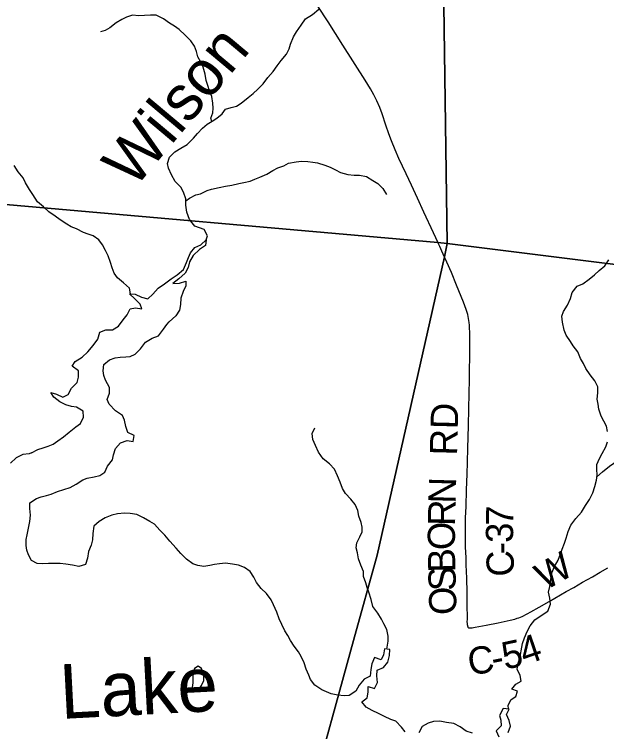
# Model space of a CAD drawing. Extents: x 0 to 34, y 0 to 22.
# Drawn here: x 3.583 to 4.817, y 18.585 to 20.079 of the extents above; entities that cross this region are included whole.
import ezdxf

# ---------------------------------------------------------------- set-up
doc = ezdxf.new("R2010")
doc.units = 0
for name, color, linetype in [('GM_X_County_Road', 7, 'Continuous'), ('GM_X_County_Road_Text', 7, 'Continuous'), ('GM_X_Major_Lake', 7, 'Continuous'), ('GM_X_Major_Lake_Text', 7, 'Continuous'), ('GM_X_Minor_River', 7, 'Continuous'), ('GM_X_Minor_River_Text', 7, 'Continuous'), ('GM_X_Township_Road', 7, 'Continuous')]:
    doc.layers.add(name, color=color, linetype=linetype)

msp = doc.modelspace()

# ---------------------------------------------------------------- linework, layer by layer
at = {"layer": 'GM_X_County_Road'}
msp.add_line((4.5241, 18.9388), (4.5239, 18.9467), dxfattribs=at)
for points in [[(4.466, 19.6027), (4.4656, 19.6036), (4.4562, 19.6242), (4.4362, 19.667), (4.4225, 19.6965), (4.41, 19.7233), (4.3991, 19.747), (4.3842, 19.7792), (4.3762, 19.7973), (4.3684, 19.8162), (4.3629, 19.8307), (4.3571, 19.8483), (4.3492, 19.8719), (4.3442, 19.8853), (4.338, 19.8996), (4.3319, 19.9119), (4.3249, 19.9244), (4.3138, 19.9424), (4.2676, 20.0153), (4.2365, 20.064), (4.215, 20.0967)], [(4.4791, 19.5737), (4.4736, 19.5858), (4.4694, 19.5954), (4.466, 19.6027)], [(4.5239, 18.9467), (4.523, 18.9697), (4.5227, 18.9921), (4.5231, 19.0305), (4.5239, 19.0542), (4.5251, 19.0887), (4.5263, 19.1212), (4.5272, 19.146), (4.5277, 19.1752), (4.5292, 19.2218), (4.5301, 19.2578), (4.5313, 19.3193), (4.5322, 19.3843), (4.5322, 19.3992), (4.5321, 19.405), (4.5318, 19.4172), (4.5315, 19.4256), (4.5312, 19.4316), (4.5306, 19.4374), (4.53, 19.4413), (4.5294, 19.4454), (4.5275, 19.454), (4.5244, 19.4642), (4.5186, 19.48), (4.5044, 19.5151), (4.4934, 19.5415), (4.4839, 19.5631), (4.4791, 19.5737)], [(4.5291, 18.8011), (4.5286, 18.802), (4.5283, 18.8028), (4.5279, 18.8039), (4.5275, 18.8056), (4.5273, 18.8068), (4.5271, 18.8094), (4.5266, 18.8143), (4.5267, 18.8183), (4.5268, 18.825), (4.5269, 18.8301), (4.5266, 18.8401), (4.5266, 18.8748), (4.5256, 18.9046), (4.5244, 18.9326), (4.5241, 18.9388)], [(4.5291, 18.8011), (4.5304, 18.8008), (4.531, 18.8007), (4.5318, 18.8007), (4.5331, 18.8007), (4.5345, 18.8008), (4.5359, 18.801), (4.537, 18.8011), (4.5393, 18.8015), (4.5431, 18.8022), (4.5503, 18.8037), (4.5659, 18.8068), (4.5908, 18.8117), (4.6157, 18.8168), (4.6258, 18.8194), (4.6306, 18.8209), (4.634, 18.822), (4.6377, 18.8235), (4.6408, 18.8249), (4.6513, 18.8301), (4.659, 18.8342), (4.6762, 18.8441), (4.6972, 18.8562), (4.7327, 18.8767), (4.7484, 18.8854), (4.7667, 18.8959), (4.7871, 18.9075), (4.8032, 18.9168), (4.8193, 18.9261)]]:
    msp.add_lwpolyline(points, dxfattribs=at)
at = {"layer": 'GM_X_Major_Lake'}
for points in [[(3.6188, 19.1659), (3.6319, 19.1726), (3.6429, 19.1761), (3.6532, 19.1797), (3.6636, 19.1841), (3.6732, 19.1907), (3.6851, 19.1992), (3.697, 19.2085), (3.7113, 19.2196), (3.7209, 19.227), (3.7272, 19.2397), (3.7263, 19.2523), (3.7121, 19.2609), (3.7023, 19.2626), (3.6899, 19.2659), (3.6775, 19.2722), (3.6652, 19.2819), (3.6589, 19.2915), (3.671, 19.2883), (3.6841, 19.2819), (3.6952, 19.287), (3.7023, 19.3002), (3.7135, 19.3125), (3.7168, 19.3234), (3.7163, 19.3367), (3.7032, 19.3461), (3.7095, 19.3558), (3.7241, 19.365), (3.7357, 19.3765), (3.7473, 19.3892), (3.7567, 19.4023), (3.7608, 19.417), (3.7734, 19.4217), (3.7874, 19.4218), (3.8001, 19.4299), (3.8094, 19.4426), (3.818, 19.4534), (3.8239, 19.4655), (3.8353, 19.4679), (3.8482, 19.4661), (3.8453, 19.4757), (3.8342, 19.4865), (3.823, 19.497), (3.8348, 19.4967), (3.8479, 19.4904), (3.8607, 19.4867), (3.8715, 19.4964), (3.8824, 19.5087), (3.8958, 19.5179), (3.9097, 19.5283), (3.9223, 19.5367), (3.9351, 19.5475), (3.9414, 19.5625), (3.9454, 19.5727), (3.9498, 19.5825), (3.9587, 19.5937), (3.9717, 19.5991), (3.9822, 19.6095), (3.9808, 19.5978), (3.9689, 19.5893), (3.9554, 19.5767), (3.9479, 19.5639), (3.945, 19.5522), (3.9387, 19.5398), (3.9256, 19.5283), (3.9129, 19.5187), (3.9269, 19.5196), (3.9403, 19.5235), (3.9401, 19.514), (3.9345, 19.5016), (3.9297, 19.488), (3.929, 19.4751), (3.9269, 19.463), (3.9191, 19.451), (3.9056, 19.4388)], [(3.6288, 19.0708), (3.6391, 19.0743), (3.6498, 19.0767), (3.6593, 19.0798), (3.6731, 19.0848), (3.6861, 19.0893), (3.6991, 19.0935), (3.7118, 19.1004), (3.7253, 19.1095), (3.7349, 19.1126), (3.749, 19.1157), (3.7608, 19.1187), (3.7713, 19.1257), (3.7769, 19.1376), (3.7875, 19.1514), (3.7897, 19.1616), (3.7939, 19.1744), (3.8041, 19.1866), (3.8178, 19.1911), (3.8303, 19.1893), (3.8322, 19.2021), (3.8195, 19.2082), (3.8149, 19.2208), (3.8126, 19.2338), (3.808, 19.2438), (3.7938, 19.2533), (3.7806, 19.2669), (3.7763, 19.2769), (3.7809, 19.2904), (3.7812, 19.3022), (3.7726, 19.3172), (3.7694, 19.3268), (3.7682, 19.3363), (3.769, 19.3496), (3.7814, 19.3595), (3.7932, 19.3637), (3.8035, 19.3649), (3.8149, 19.3657), (3.8244, 19.3666), (3.8344, 19.3716), (3.8457, 19.3827), (3.8563, 19.3965), (3.8702, 19.4044), (3.8832, 19.4094), (3.8938, 19.4235), (3.9009, 19.4332), (3.9056, 19.4388)], [(3.6188, 19.1659), (3.6136, 19.1638), (3.6007, 19.1623), (3.5869, 19.1554), (3.5748, 19.1444)], [(4.318, 18.6549), (4.3199, 18.667), (4.3202, 18.6787), (4.333, 18.6746), (4.3398, 18.6869), (4.3383, 18.701), (4.3386, 18.7127), (4.3517, 18.7185), (4.3607, 18.7296), (4.3645, 18.7431), (4.3649, 18.756), (4.3543, 18.7575), (4.352, 18.7446), (4.3468, 18.7345), (4.3333, 18.7391), (4.3276, 18.7263), (4.3254, 18.7139), (4.3239, 18.7003), (4.3119, 18.6938), (4.301, 18.6815), (4.2942, 18.6692), (4.2803, 18.6601), (4.27, 18.6596), (4.2568, 18.6608), (4.2433, 18.6638), (4.2331, 18.6675), (4.2234, 18.6719), (4.2089, 18.6814), (4.1998, 18.6931), (4.1963, 18.7026), (4.1909, 18.7146), (4.1868, 18.7283), (4.1807, 18.7414), (4.1749, 18.751), (4.1662, 18.7627), (4.1582, 18.7743), (4.1524, 18.7851), (4.1466, 18.7951), (4.1402, 18.8078), (4.1349, 18.8201), (4.1296, 18.8335), (4.1228, 18.8488), (4.1182, 18.8596), (4.1083, 18.8728), (4.0973, 18.8829), (4.0874, 18.8954), (4.082, 18.9069), (4.0744, 18.9181), (4.0622, 18.9268), (4.0502, 18.9313), (4.0374, 18.9339), (4.0226, 18.9355), (4.0101, 18.9343), (3.9998, 18.9331), (3.9899, 18.9307), (3.9778, 18.9291), (3.9649, 18.931), (3.9548, 18.9343), (3.9414, 18.9438), (3.93, 18.9559), (3.9201, 18.9671), (3.9069, 18.9819), (3.8967, 18.994), (3.8863, 19.0045), (3.8746, 19.017), (3.8649, 19.0229), (3.8522, 19.0305), (3.8384, 19.0369), (3.8245, 19.0392), (3.8124, 19.0399), (3.7979, 19.0388), (3.7857, 19.0357), (3.7719, 19.0304), (3.7596, 19.0228), (3.7487, 19.0129), (3.7464, 18.9977), (3.746, 18.9841), (3.7426, 18.9732), (3.7373, 18.9601), (3.735, 18.9461), (3.7313, 18.9333), (3.7175, 18.9291), (3.7043, 18.9314), (3.6904, 18.934), (3.6783, 18.9348), (3.6635, 18.9352), (3.654, 18.9351), (3.6415, 18.9343), (3.6306, 18.9353), (3.6186, 18.941), (3.6121, 18.9533), (3.609, 18.9632), (3.6074, 18.9728), (3.6077, 18.9849), (3.6099, 18.9951), (3.6126, 19.0087), (3.6153, 19.0226), (3.6164, 19.0359), (3.6153, 19.0496), (3.6149, 19.0617), (3.6288, 19.0708)], [(3.9779, 18.699), (3.978, 18.7048), (3.9726, 18.7162), (3.9662, 18.7213), (3.9582, 18.7165), (3.9549, 18.706), (3.9548, 18.6984)], [(3.9548, 18.6984), (3.9549, 18.6866), (3.9536, 18.6764), (3.956, 18.668), (3.9656, 18.6705), (3.973, 18.6806), (3.9777, 18.6915), (3.9779, 18.699)], [(4.3971, 18.584), (4.3898, 18.5937), (4.378, 18.6062), (4.3675, 18.6103), (4.3544, 18.6163), (4.3417, 18.6224), (4.3286, 18.6288), (4.3156, 18.6356), (4.3072, 18.6468), (4.318, 18.6549)], [(4.6118, 18.583), (4.6167, 18.5958), (4.614, 18.6076), (4.6083, 18.6203), (4.614, 18.6315), (4.6015, 18.6326), (4.5935, 18.6184), (4.5963, 18.6089), (4.5974, 18.5967), (4.5865, 18.5867), (4.5922, 18.5737)], [(4.5371, 18.5817), (4.524, 18.5854), (4.5114, 18.5945), (4.4987, 18.6017), (4.4836, 18.604), (4.4693, 18.6063), (4.4564, 18.6055), (4.4449, 18.6024), (4.4326, 18.5952), (4.4258, 18.5821)]]:
    msp.add_lwpolyline(points, dxfattribs=at)
at = {"layer": 'GM_X_Minor_River'}
for points in [[(3.9822, 19.6094), (3.9854, 19.6178), (3.9785, 19.6312), (3.9687, 19.6345), (3.9589, 19.6384), (3.9478, 19.6519), (3.9421, 19.6672), (3.9401, 19.6817), (3.94, 19.6953), (3.9354, 19.7091), (3.9295, 19.7191), (3.918, 19.7311), (3.91, 19.7453), (3.9038, 19.759), (3.9021, 19.7686), (3.9058, 19.7818), (3.9174, 19.7929), (3.93, 19.8003), (3.9431, 19.808), (3.9558, 19.8214), (3.9644, 19.8314), (3.9748, 19.8422), (3.9845, 19.8508), (3.9952, 19.857), (4.0048, 19.8633), (4.0156, 19.8722), (4.023, 19.8819), (4.0344, 19.8851), (4.0455, 19.8883), (4.0555, 19.8941), (4.0697, 19.906), (4.0805, 19.9145), (4.0905, 19.9238), (4.101, 19.935), (4.1107, 19.9477), (4.1224, 19.9607), (4.1306, 19.9723), (4.1391, 19.9835), (4.1496, 19.9966), (4.1552, 20.0075), (4.1584, 20.0173), (4.1648, 20.0324), (4.171, 20.0432), (4.1804, 20.0571), (4.1898, 20.0698), (4.204, 20.0794), (4.2175, 20.0905)], [(3.9944, 19.8565), (3.9923, 19.8631), (3.9967, 19.8744), (3.9973, 19.8843), (3.9967, 19.8942), (3.994, 19.9083), (3.9897, 19.9193), (3.9868, 19.9289), (3.9826, 19.9415), (3.9806, 19.9548), (3.9763, 19.9697), (3.9712, 19.98), (3.9654, 19.9912), (3.9626, 20.0022), (3.9583, 20.0129), (3.9505, 20.0241), (3.939, 20.0364), (3.926, 20.0477), (3.9163, 20.0547), (3.9062, 20.061), (3.8935, 20.07), (3.8781, 20.0775), (3.8668, 20.0781), (3.8539, 20.0768), (3.8421, 20.0767), (3.8289, 20.0777), (3.8163, 20.0738), (3.8067, 20.0687), (3.7952, 20.0621), (3.7821, 20.0513), (3.7722, 20.0458), (3.7626, 20.0433)], [(3.8249, 19.4969), (3.8225, 19.5091), (3.8106, 19.5203), (3.7976, 19.5301), (3.7906, 19.5401), (3.787, 19.5515), (3.7831, 19.5622), (3.7781, 19.5764), (3.773, 19.5871), (3.7668, 19.599), (3.7587, 19.6094), (3.7471, 19.6176), (3.7369, 19.6216), (3.7268, 19.6252), (3.7122, 19.6323), (3.7016, 19.6367), (3.6919, 19.6422), (3.6781, 19.6512), (3.6676, 19.659), (3.6545, 19.6676), (3.6434, 19.6785), (3.6311, 19.6886), (3.6216, 19.7043), (3.6146, 19.7143), (3.6061, 19.7281), (3.6011, 19.7389), (3.5911, 19.7512), (3.5826, 19.7643)], [(3.94, 19.6912), (3.948, 19.6963), (3.961, 19.7033), (3.9705, 19.7057), (3.9843, 19.7127), (3.9938, 19.7155), (4.0094, 19.7186), (4.0231, 19.7214), (4.0357, 19.7238), (4.0505, 19.7273), (4.0608, 19.7294), (4.0741, 19.7321), (4.084, 19.7357), (4.0944, 19.7405), (4.1089, 19.7466), (4.1212, 19.754), (4.1319, 19.7598), (4.1441, 19.7638), (4.154, 19.7693), (4.17, 19.7724), (4.1814, 19.7737), (4.1943, 19.7726), (4.2045, 19.7717), (4.2143, 19.7703), (4.2301, 19.7651), (4.2406, 19.7611), (4.2523, 19.7552), (4.2624, 19.75), (4.2774, 19.7456), (4.2907, 19.7446), (4.3021, 19.7447), (4.3164, 19.7418), (4.3299, 19.7335), (4.3403, 19.7269), (4.3507, 19.7164), (4.3584, 19.7038)], [(4.8184, 19.2102), (4.8164, 19.2212), (4.8113, 19.2319), (4.8055, 19.2423), (4.8008, 19.2564), (4.7995, 19.2671), (4.7975, 19.2774), (4.7985, 19.2906), (4.7984, 19.3035), (4.7926, 19.3161), (4.7826, 19.3281), (4.7738, 19.3412), (4.7687, 19.3519), (4.7625, 19.3623), (4.7571, 19.376), (4.7475, 19.3884), (4.7416, 19.398), (4.7328, 19.4107), (4.7284, 19.4214), (4.7246, 19.4378), (4.7237, 19.4503), (4.727, 19.4605), (4.7352, 19.4736), (4.7419, 19.4871), (4.7452, 19.4996), (4.7553, 19.5127), (4.7672, 19.5181), (4.7806, 19.5273), (4.7918, 19.537), (4.8014, 19.5455), (4.8134, 19.5555), (4.8212, 19.5679)], [(4.7964, 19.1159), (4.808, 19.1261), (4.8226, 19.1376), (4.8322, 19.1443), (4.8419, 19.1532), (4.8523, 19.1632), (4.8628, 19.1774), (4.8741, 19.189), (4.8841, 19.1956), (4.8978, 19.201), (4.9092, 19.2031), (4.9222, 19.2081), (4.9348, 19.2147), (4.9444, 19.2202), (4.9603, 19.2282)], [(4.359, 18.7568), (4.362, 18.7734), (4.3615, 18.7837), (4.3591, 18.7974), (4.3529, 18.8092), (4.3475, 18.8192), (4.3405, 18.8315), (4.3298, 18.8458), (4.3263, 18.8599), (4.3213, 18.8755), (4.3181, 18.8851), (4.3153, 18.8946), (4.3106, 18.908), (4.3105, 18.9182), (4.3047, 18.9316), (4.3, 18.9446), (4.2976, 18.9572), (4.2948, 18.9675), (4.2965, 18.9781), (4.3025, 18.9905), (4.3076, 19.001), (4.3078, 19.0105), (4.3057, 19.0204), (4.3007, 19.0337), (4.2983, 19.0456), (4.2933, 19.0578), (4.2836, 19.0694), (4.2729, 19.0813), (4.2663, 19.0913), (4.262, 19.1047), (4.2562, 19.1181), (4.2501, 19.1315), (4.2397, 19.1427), (4.2266, 19.1532), (4.2167, 19.1671), (4.2105, 19.1808), (4.2047, 19.1935), (4.2031, 19.206), (4.2087, 19.2181)], [(4.6126, 18.6316), (4.6116, 18.6402), (4.6179, 18.6519), (4.6279, 18.6577), (4.6315, 18.669), (4.6195, 18.6735), (4.6277, 18.6835), (4.6388, 18.6902), (4.6364, 18.702), (4.6306, 18.715), (4.6327, 18.7271), (4.6368, 18.7407), (4.6386, 18.7528), (4.6419, 18.7682), (4.6459, 18.7803), (4.6515, 18.7931), (4.6578, 18.8051), (4.6672, 18.8174), (4.6806, 18.827), (4.6941, 18.8359), (4.6997, 18.8506), (4.6984, 18.8627), (4.696, 18.8753), (4.6985, 18.8874), (4.7003, 18.9018), (4.7025, 18.9158), (4.7085, 18.9285), (4.7156, 18.9417), (4.7208, 18.9549), (4.724, 18.965), (4.7292, 18.9778), (4.7328, 18.9876), (4.7369, 19.002), (4.7421, 19.0151), (4.7526, 19.029), (4.7642, 19.042), (4.7732, 19.0559), (4.7814, 19.0682), (4.7881, 19.0821), (4.7922, 19.0957), (4.7955, 19.1086), (4.7969, 19.1192), (4.7964, 19.1317), (4.7966, 19.1412), (4.8017, 19.1536), (4.8073, 19.1645), (4.8151, 19.178), (4.8188, 19.1889)]]:
    msp.add_lwpolyline(points, dxfattribs=at)
at = {"layer": 'GM_X_Township_Road'}
for points in [[(4.4664, 20.9), (2.1, 20.9), (2.1, 20.7431), (2.3144, 20.5665), (3.1019, 19.912), (3.1735, 19.8394), (3.4805, 19.8366), (3.501, 19.6889), (4.4654, 19.6041), (4.4849, 19.6021), (4.4684, 20.7448)], [(8.9, 19.1426), (8.9, 20.9), (4.4664, 20.9), (4.4684, 20.7448), (4.4849, 19.6021), (5.1411, 19.5203), (5.6889, 19.4592), (5.8809, 19.4409), (6.3561, 19.3959), (7.1834, 19.2978), (7.8888, 19.2268), (8.4186, 19.1875)]]:
    msp.add_lwpolyline(points, close=True, dxfattribs=at)
for points in [[(3.7787, 17.0143), (3.7921, 17.074), (3.9903, 17.6899), (4.0744, 17.9948), (4.1901, 18.4135), (4.1943, 18.4289), (4.2897, 18.7747), (4.3389, 18.9527), (4.4789, 19.5742), (4.4849, 19.6021), (4.4654, 19.6041), (3.501, 19.6889), (3.4805, 19.8366), (3.1735, 19.8394), (3.1019, 19.912), (2.3144, 20.5665), (2.1, 20.7431), (2.1, 15.597), (2.2517, 15.5643), (3.1228, 15.3686), (3.3385, 15.3189), (3.6691, 16.5264), (3.7277, 16.7873)], [(8.9, 16.5763), (8.9, 19.1426), (8.4186, 19.1875), (7.8888, 19.2268), (7.1834, 19.2978), (6.3561, 19.3959), (5.8809, 19.4409), (5.6889, 19.4592), (5.1411, 19.5203), (4.4849, 19.6021), (4.4789, 19.5742), (4.3389, 18.9527), (4.2897, 18.7747), (4.1943, 18.4289), (4.1901, 18.4135), (4.0744, 17.9948), (3.9903, 17.6899), (3.7921, 17.074)]]:
    msp.add_lwpolyline(points, dxfattribs=at)

# ---------------------------------------------------------------- texts
at = {"layer": 'GM_X_County_Road_Text'}
for s, height, rotation, p in [('RD', 0.05682, 88.5264, (4.5052, 19.1596)), ('N', 0.0568, 88.4007, (4.5021, 19.0594)), ('R', 0.0568, 88.6416, (4.501, 19.0128)), ('7', 0.0568, 88.7275, (4.622, 19.0128)), ('O', 0.0568, 90.0911, (4.501, 18.9631)), ('3', 0.0568, 90.3253, (4.6222, 18.9782)), ('-', 0.0568, 91.4559, (4.6228, 18.9551)), ('B', 0.0568, 91.3271, (4.5021, 18.9168)), ('C', 0.0568, 92.0925, (4.6245, 18.9087)), ('W', 0.0568, 29.7452, (4.6891, 18.8778)), ('S', 0.0568, 91.4612, (4.5031, 18.8785)), ('O', 0.0568, 91.4627, (4.5044, 18.8285)), ('5', 0.0568, 11.9302, (4.605, 18.7138)), ('4', 0.0568, 18.7893, (4.6464, 18.723)), ('C', 0.0568, 7.5152, (4.5312, 18.7022)), ('-', 0.0568, 11.531, (4.5817, 18.709))]:
    msp.add_text(s, height=height, rotation=rotation, dxfattribs=at).set_placement(p)
at = {"layer": 'GM_X_Major_Lake_Text'}
msp.add_text('Lake', height=0.11363, rotation=2.9988, dxfattribs=at).set_placement((3.6803, 18.6111))
at = {"layer": 'GM_X_Minor_River_Text'}
msp.add_text('Wilson', height=0.0947, rotation=49.9977, dxfattribs=at).set_placement((3.8324, 19.714))

doc.saveas('drawing.dxf')
